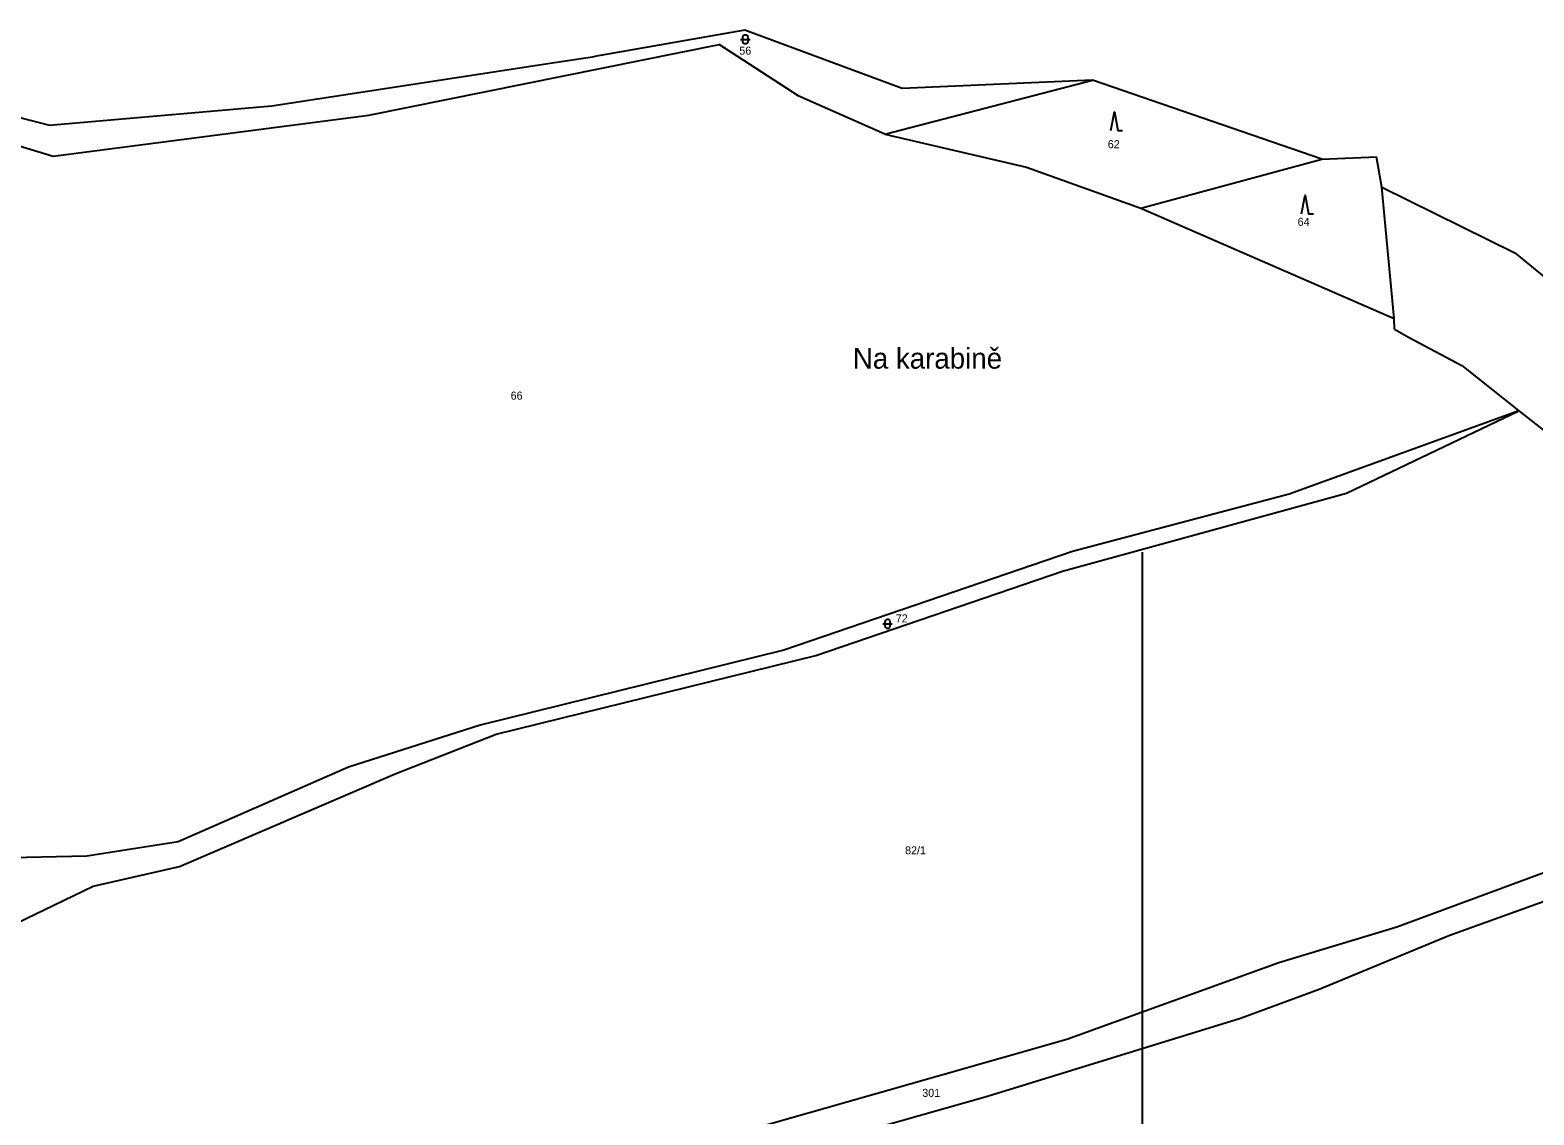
# Model space of a CAD drawing. Extents: x -780000 to -777378, y -1011169 to -1009297.
# Drawn here: x -778986.4 to -778666.9, y -1010119.6 to -1009889 of the extents above; entities that cross this region are included whole.
import ezdxf

# ---------------------------------------------------------------- set-up
doc = ezdxf.new("R2010")
doc.units = 0
for name, color, linetype in [('Default', 7, 'Continuous'), ('KLADY_ZMVM', 7, 'Continuous'), ('KN_HRANICE', 7, 'Continuous'), ('KN_KULTURY', 7, 'Continuous'), ('KN_PARCELY', 7, 'Continuous')]:
    doc.layers.add(name, color=color, linetype=linetype)

# ---------------------------------------------------------------- blocks, each defined once
blk = doc.blocks.new('308')
at = {"layer": 'Default'}
blk.add_lwpolyline([(-0.75, 0), (0, 4), (0.75, 0), (1.75, 0)], dxfattribs=at)
blk = doc.blocks.new('316')
at = {"layer": 'Default'}
for points in [[(-1, 1), (0.27, 1), (1, 1)], [(-0.5, 1.5), (-0.4, 1.79), (-0.15, 1.97), (0.16, 1.97), (0.41, 1.79), (0.51, 1.5), (0.51, 0.5), (0.41, 0.21), (0.16, 0.03), (-0.15, 0.03), (-0.4, 0.21), (-0.5, 0.5), (-0.5, 1.5)]]:
    blk.add_lwpolyline(points, dxfattribs=at)

msp = doc.modelspace()

# ---------------------------------------------------------------- linework, layer by layer
at = {"layer": 'KLADY_ZMVM'}
msp.add_lwpolyline([(-779108.78, -1010500), (-778750, -1010500), (-778750, -1010000)], dxfattribs=at)
at = {"layer": 'KN_HRANICE'}
for p, q in [((-778834.56, -1009889.02), (-778866.47, -1009894.62)), ((-778801.13, -1009901.44), (-778834.56, -1009889.02)), ((-778914.43, -1009907.12), (-778840, -1009892.06)), ((-778823.02, -1009903.04), (-778840, -1009892.06)), ((-778935.03, -1009905.15), (-778874.97, -1009895.93)), ((-778874.97, -1009895.93), (-778866.47, -1009894.62)), ((-778804.81, -1009911.11), (-778760.64, -1009899.67)), ((-778760.64, -1009899.67), (-778801.13, -1009901.44)), ((-778711.94, -1009916.46), (-778760.64, -1009899.67)), ((-778804.81, -1009911.11), (-778823.02, -1009903.04)), ((-778995.28, -1009905.9), (-778982.29, -1009909.24)), ((-778982.29, -1009909.24), (-778935.03, -1009905.15)), ((-778981.54, -1009915.82), (-778914.43, -1009907.12)), ((-778995.73, -1009911.49), (-778981.54, -1009915.82)), ((-778804.81, -1009911.11), (-778774.65, -1009918.18)), ((-778750.38, -1009926.85), (-778711.94, -1009916.46)), ((-778711.94, -1009916.46), (-778700.3, -1009915.96)), ((-778699.18, -1009922.39), (-778700.3, -1009915.96)), ((-778774.65, -1009918.18), (-778750.38, -1009926.85)), ((-778699.18, -1009922.39), (-778670.88, -1009936.37)), ((-778696.54, -1009950.3), (-778699.18, -1009922.39)), ((-778750.38, -1009926.85), (-778696.54, -1009950.3)), ((-778670.88, -1009936.37), (-778642.47, -1009959.73)), ((-778696.47, -1009952.58), (-778696.54, -1009950.3)), ((-778696.47, -1009952.58), (-778693.5, -1009954.31)), ((-778693.5, -1009954.31), (-778682.19, -1009960.32)), ((-778682.19, -1009960.32), (-778670.06, -1009969.95)), ((-778670.06, -1009969.95), (-778718.88, -1009987.64)), ((-778706.66, -1009987.42), (-778670.06, -1009969.95)), ((-778670.06, -1009969.95), (-778648.43, -1009986.95)), ((-778767.02, -1010004.01), (-778706.66, -1009987.42)), ((-778718.88, -1009987.64), (-778764.89, -1009999.85)), ((-778764.89, -1009999.85), (-778826.21, -1010020.79)), ((-778819.45, -1010021.97), (-778767.02, -1010004.01)), ((-778826.21, -1010020.79), (-778890.8, -1010036.76)), ((-778887.38, -1010038.7), (-778819.45, -1010021.97)), ((-778890.8, -1010036.76), (-778918.78, -1010045.67)), ((-778908.85, -1010047.11), (-778887.38, -1010038.7)), ((-778918.78, -1010045.67), (-778954.93, -1010061.53)), ((-778954.68, -1010066.8), (-778908.85, -1010047.11)), ((-778695.97, -1010079.62), (-778608.15, -1010047.05)), ((-778684.92, -1010081.46), (-778622.94, -1010059.11)), ((-778954.93, -1010061.53), (-778974.33, -1010064.63)), ((-778974.33, -1010064.63), (-778993.67, -1010065.04)), ((-778973, -1010070.94), (-778954.68, -1010066.8)), ((-778994.71, -1010081.37), (-778973, -1010070.94)), ((-778721.06, -1010087.16), (-778695.97, -1010079.62)), ((-778712.5, -1010092.84), (-778684.92, -1010081.46)), ((-778766.08, -1010103.5), (-778721.06, -1010087.16)), ((-778729.23, -1010099), (-778712.5, -1010092.84)), ((-778782.95, -1010115.6), (-778729.23, -1010099)), ((-778869.36, -1010132.88), (-778766.08, -1010103.5)), ((-778810.44, -1010123.41), (-778782.95, -1010115.6))]:
    msp.add_line(p, q, dxfattribs=at)

# ---------------------------------------------------------------- block references
at = {"layer": 'KN_KULTURY'}
for name, p in [('316', (-778834.43, -1009891.99)), ('308', (-778756, -1009910.4)), ('308', (-778715.47, -1009928.08)), ('316', (-778804.2, -1010016.21))]:
    msp.add_blockref(name, p, dxfattribs=at)

# ---------------------------------------------------------------- texts
at = {"layer": 'KN_PARCELY'}
for s, height, p in [('56', 1.7, (-778835.7, -1009894.24)), ('62', 1.7, (-778757.4, -1009914.12)), ('64', 1.7, (-778717.06, -1009930.63)), ('Na karabině', 4.4, (-778811.59, -1009960.98)), ('66', 1.7, (-778884.29, -1009967.56)), ('72', 1.7, (-778802.45, -1010014.91)), ('82/1', 1.7, (-778800.47, -1010064.2)), ('301', 1.7, (-778796.82, -1010115.75))]:
    msp.add_text(s, height=height, dxfattribs=at).set_placement(p)

doc.saveas('drawing.dxf')
